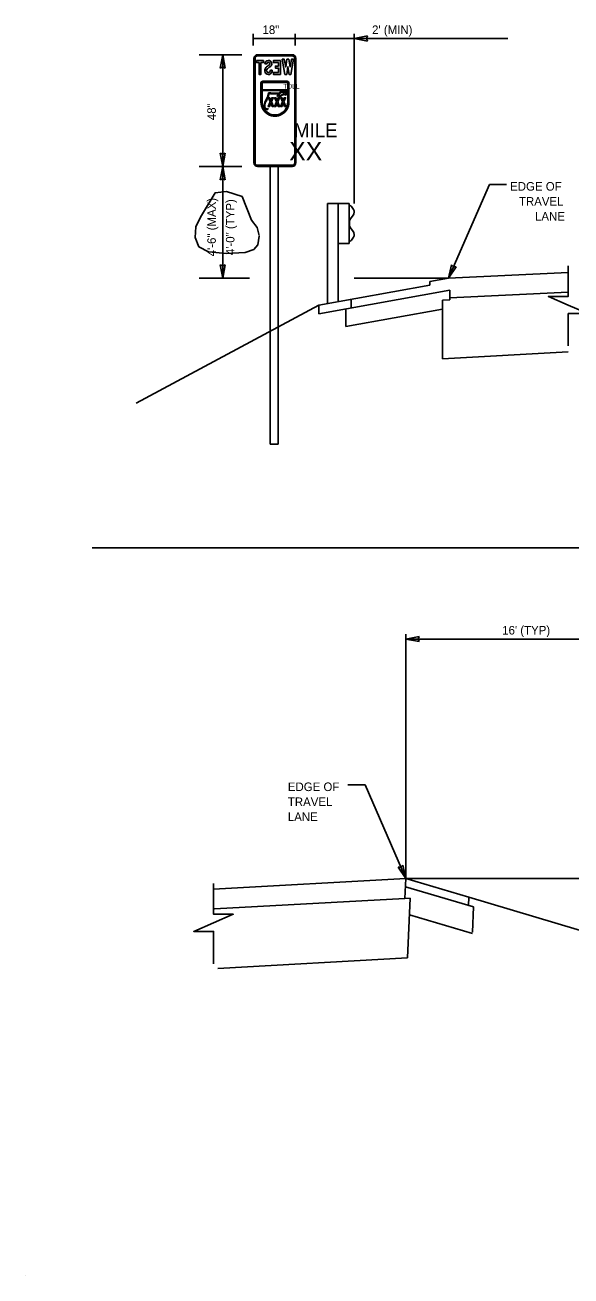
# Model space of a CAD drawing. Extents: x 56768 to 57406, y 11696 to 12105.
# Drawn here: x 56767.9 to 56946.4, y 11696.3 to 12105.2 of the extents above; entities that cross this region are included whole.
import ezdxf

# ---------------------------------------------------------------- set-up
doc = ezdxf.new("R2010")
doc.units = 0
for name, color, linetype in [('1', 7, 'Continuous'), ('52', 7, 'Continuous'), ('62', 7, 'Continuous'), ('AdhocPoint_dp', 7, 'Continuous'), ('Default', 7, 'Continuous'), ('DimLines_dp', 7, 'Continuous'), ('SheetBorder_dp', 7, 'Continuous'), ('SignPanel', 7, 'Continuous'), ('XSGrdLine_ex', 7, 'Continuous')]:
    doc.layers.add(name, color=color, linetype=linetype)

msp = doc.modelspace()

# ---------------------------------------------------------------- linework, layer by layer
at = {"layer": '1'}
for p, q in [((56848.03, 12005.09), (56848.03, 12058.97)), ((56850.69, 12006.52), (56850.69, 12058.97)), ((56848.03, 11968.2), (56848.03, 12005.09)), ((56850.69, 11968.2), (56850.69, 12006.52)), ((56850.69, 11968.2), (56848.03, 11968.2))]:
    msp.add_line(p, q, dxfattribs=at)
at = {"layer": '52'}
for p, q in [((56824.81, 12022.47), (56841.31, 12022.47)), ((56875.53, 12022.47), (56906.41, 12022.47)), ((56970.53, 11826.22), (56892.41, 11826.22))]:
    msp.add_line(p, q, dxfattribs=at)
at = {"layer": '62'}
msp.add_lwpolyline([(56844.47, 12036.41), (56843.77, 12039.01), (56841.97, 12041.42), (56838.86, 12049.17), (56833.76, 12050.77), (56830.06, 12050.27), (56825.26, 12042.42), (56823.76, 12039.21), (56823.56, 12035.71), (56824.76, 12032.7), (56827.86, 12031), (56833.76, 12030.5), (56839.86, 12030.8), (56842.67, 12031.8), (56844.07, 12033.31), (56844.47, 12036.21)], dxfattribs=at)
at = {"layer": 'AdhocPoint_dp'}
msp.add_line((56767.89, 11696.32), (56767.89, 11696.32), dxfattribs=at)
at = {"layer": 'Default'}
for points in [[(56945.5, 12000.28), (56945.5, 12010.84), (56951.96, 12010.84), (56945.5, 12013.65), (56939.04, 12016.47), (56945.5, 12016.47), (56945.5, 12026.47)], [(56829.53, 11798.37), (56829.53, 11808.93), (56823.07, 11808.93), (56829.53, 11811.74), (56835.99, 11814.56), (56829.53, 11814.56), (56829.53, 11824.56)]]:
    msp.add_lwpolyline(points, dxfattribs=at)
at = {"layer": 'DimLines_dp'}
for p, q in [((56842.51, 12098.47), (56842.51, 12102.3)), ((56856.2, 12098.47), (56856.2, 12102.3)), ((56875.53, 12046.89), (56875.53, 12102.3)), ((56856.2, 12100.75), (56842.51, 12100.75)), ((56856.2, 12100.75), (56925.74, 12100.75)), ((56875.53, 12100.75), (56879.88, 12101.59)), ((56879.88, 12099.94), (56875.53, 12100.75)), ((56879.88, 12101.59), (56879.55, 12100.75)), ((56879.55, 12100.75), (56879.88, 12099.94)), ((56824.81, 12095.47), (56838.74, 12095.47)), ((56831.74, 12091.12), (56832.55, 12095.47)), ((56832.55, 12095.47), (56832.55, 12058.97)), ((56832.55, 12095.47), (56833.39, 12091.12)), ((56832.55, 12091.45), (56831.74, 12091.12)), ((56833.39, 12091.12), (56832.55, 12091.45)), ((56832.55, 12058.97), (56831.71, 12063.32)), ((56831.71, 12063.32), (56832.55, 12062.99)), ((56832.55, 12058.97), (56831.71, 12063.32)), ((56831.71, 12063.32), (56832.55, 12062.99)), ((56832.55, 12062.99), (56833.36, 12063.32)), ((56833.36, 12063.32), (56832.55, 12058.97)), ((56832.55, 12062.99), (56833.36, 12063.32)), ((56833.36, 12063.32), (56832.55, 12058.97)), ((56824.81, 12058.97), (56838.74, 12058.97)), ((56831.74, 12054.62), (56832.55, 12058.97)), ((56832.55, 12058.97), (56832.55, 12022.47)), ((56832.55, 12058.97), (56833.39, 12054.62)), ((56832.55, 12054.95), (56831.74, 12054.62)), ((56833.39, 12054.62), (56832.55, 12054.95)), ((56919.73, 12053.08), (56906.41, 12022.46)), ((56925.38, 12053.08), (56919.73, 12053.08)), ((56832.55, 12022.47), (56831.71, 12026.82)), ((56831.71, 12026.82), (56832.55, 12026.49)), ((56832.55, 12026.49), (56833.36, 12026.82)), ((56833.36, 12026.82), (56832.55, 12022.47)), ((56906.41, 12022.46), (56907.37, 12026.79)), ((56908.89, 12026.13), (56906.41, 12022.46)), ((56907.37, 12026.79), (56908.01, 12026.15)), ((56908.01, 12026.15), (56908.89, 12026.13)), ((56892.41, 11826.22), (56892.41, 11906.05)), ((56896.76, 11905.31), (56892.41, 11904.5)), ((56892.41, 11904.5), (56896.76, 11903.66)), ((56973.53, 11904.5), (56892.41, 11904.5)), ((56896.43, 11904.5), (56896.76, 11905.31)), ((56896.76, 11903.66), (56896.43, 11904.5)), ((56873.44, 11856.84), (56879.09, 11856.84)), ((56879.09, 11856.84), (56892.41, 11826.22)), ((56890.8, 11829.91), (56889.93, 11829.89)), ((56889.93, 11829.89), (56892.41, 11826.22)), ((56891.44, 11830.55), (56890.8, 11829.91)), ((56892.41, 11826.22), (56891.44, 11830.55))]:
    msp.add_line(p, q, dxfattribs=at)
at = {"layer": 'SheetBorder_dp'}
msp.add_line((57405.89, 11934.25), (56789.89, 11934.25), dxfattribs=at)
at = {"layer": 'SignPanel'}
for p, q in [((56846.91, 12092.46), (56846.3, 12092.46)), ((56846.91, 12092.46), (56846.3, 12092.46)), ((56846.91, 12092.46), (56846.3, 12092.46)), ((56848.11, 12090.45), (56848.73, 12090.45)), ((56848.11, 12090.45), (56848.73, 12090.45)), ((56848.11, 12090.45), (56848.73, 12090.45)), ((56845.04, 12079.95), (56845.04, 12086.23)), ((56845.24, 12079.95), (56845.24, 12086.23)), ((56845.43, 12083.95), (56845.43, 12086.23)), ((56853.6, 12086.8), (56845.61, 12086.8)), ((56853.6, 12086.61), (56845.61, 12086.61)), ((56853.6, 12086.42), (56845.61, 12086.42)), ((56853.79, 12083.95), (56853.79, 12086.23)), ((56853.98, 12079.95), (56853.98, 12086.23)), ((56854.17, 12079.95), (56854.17, 12086.23)), ((56853.79, 12083.95), (56845.43, 12083.95)), ((56845.43, 12079.95), (56845.43, 12083.76)), ((56853.79, 12083.76), (56845.43, 12083.76)), ((56847.49, 12083.02), (56847.16, 12081.58)), ((56847.38, 12081.5), (56847.68, 12082.79)), ((56848.23, 12083.02), (56847.49, 12083.02)), ((56847.68, 12082.79), (56848.11, 12082.79)), ((56848.11, 12082.79), (56848.21, 12082.63)), ((56848.21, 12082.63), (56851.22, 12082.63)), ((56848.33, 12082.86), (56848.23, 12083.02)), ((56851.06, 12082.86), (56848.33, 12082.86)), ((56850.77, 12082.34), (56850.27, 12082)), ((56850.27, 12082), (56850.4, 12081.81)), ((56850.4, 12081.81), (56850.77, 12082.07)), ((56851.38, 12081.98), (56850.77, 12082.34)), ((56850.77, 12082.07), (56851.41, 12081.7)), ((56851.19, 12083.21), (56851.06, 12082.86)), ((56853.57, 12083.39), (56851.19, 12083.21)), ((56851.22, 12082.63), (56851.36, 12082.99)), ((56851.36, 12082.99), (56853.3, 12083.14)), ((56851.83, 12082.4), (56851.38, 12081.98)), ((56851.41, 12081.7), (56851.95, 12082.19)), ((56852.75, 12082.7), (56851.83, 12082.4)), ((56851.95, 12082.19), (56852.7, 12082.44)), ((56852.32, 12083.05), (56852.32, 12083.05)), ((56852.7, 12082.44), (56852.95, 12082.24)), ((56853.02, 12082.48), (56852.75, 12082.7)), ((56852.95, 12082.24), (56853.41, 12082.3)), ((56853.2, 12082.51), (56853.02, 12082.48)), ((56853.3, 12083.14), (56853.2, 12082.51)), ((56853.41, 12082.3), (56853.57, 12083.39)), ((56853.79, 12079.95), (56853.79, 12083.76)), ((56846.3, 12080), (56846.05, 12079.08)), ((56846.05, 12079.08), (56846.05, 12078.21)), ((56846.05, 12078.21), (56846.8, 12077.6)), ((56846.28, 12079.05), (56846.51, 12079.91)), ((56846.28, 12078.32), (56846.28, 12079.05)), ((56846.9, 12077.81), (56846.28, 12078.32)), ((56846.71, 12080.67), (56846.3, 12080)), ((56846.51, 12079.91), (56846.94, 12080.61)), ((56847.16, 12081.58), (56846.71, 12080.86)), ((56846.71, 12080.86), (56846.71, 12080.67)), ((56846.8, 12077.6), (56847.16, 12077.51)), ((56847.11, 12077.76), (56846.9, 12077.81)), ((56846.94, 12080.79), (56847.38, 12081.5)), ((56846.94, 12080.61), (56846.94, 12080.79)), ((56847.25, 12077.86), (56847.11, 12077.76)), ((56847.16, 12077.51), (56847.38, 12077.67)), ((56847.38, 12077.67), (56847.25, 12077.86))]:
    msp.add_line(p, q, dxfattribs=at)
for points in [[(56842.76, 12094.33), (56842.76, 12060.11)], [(56843.14, 12094.33), (56843.14, 12060.11)], [(56855.31, 12095.47), (56843.9, 12095.47)], [(56855.31, 12095.09), (56843.9, 12095.09)], [(56856.07, 12060.11), (56856.07, 12094.33)], [(56856.45, 12060.11), (56856.45, 12094.33)], [(56843.9, 12059.35), (56855.31, 12059.35)], [(56843.9, 12058.97), (56855.31, 12058.97)]]:
    msp.add_lwpolyline(points, dxfattribs=at)
for points in [[(56854.54, 12091.43), (56854.14, 12093.99), (56853.53, 12093.99), (56853.13, 12091.43), (56852.68, 12093.99), (56851.98, 12093.99), (56852.86, 12089.04), (56853.45, 12089.04), (56853.84, 12091.52), (56854.23, 12089.04), (56854.81, 12089.04), (56855.69, 12093.99), (56855, 12093.99)], [(56854.54, 12091.43), (56854.14, 12093.99), (56853.53, 12093.99), (56853.13, 12091.43), (56852.68, 12093.99), (56851.98, 12093.99), (56852.86, 12089.04), (56853.45, 12089.04), (56853.84, 12091.52), (56854.23, 12089.04), (56854.81, 12089.04), (56855.69, 12093.99), (56855, 12093.99)], [(56854.54, 12091.43), (56854.14, 12093.99), (56853.53, 12093.99), (56853.13, 12091.43), (56852.68, 12093.99), (56851.98, 12093.99), (56852.86, 12089.04), (56853.45, 12089.04), (56853.84, 12091.52), (56854.23, 12089.04), (56854.81, 12089.04), (56855.69, 12093.99), (56855, 12093.99)], [(56845.05, 12092.91), (56845.87, 12092.91), (56845.87, 12093.54), (56843.61, 12093.54), (56843.61, 12092.91), (56844.43, 12092.91), (56844.43, 12089.04), (56845.05, 12089.04)], [(56845.05, 12092.91), (56845.87, 12092.91), (56845.87, 12093.54), (56843.61, 12093.54), (56843.61, 12092.91), (56844.43, 12092.91), (56844.43, 12089.04), (56845.05, 12089.04)], [(56845.05, 12092.91), (56845.87, 12092.91), (56845.87, 12093.54), (56843.61, 12093.54), (56843.61, 12092.91), (56844.43, 12092.91), (56844.43, 12089.04), (56845.05, 12089.04)], [(56850.76, 12089.67), (56850.76, 12091.11), (56849.79, 12091.11), (56849.79, 12091.74), (56850.76, 12091.74), (56850.76, 12092.91), (56849.12, 12092.91), (56849.12, 12093.54), (56851.38, 12093.54), (56851.38, 12089.04), (56849.12, 12089.04), (56849.12, 12089.67)], [(56850.76, 12089.67), (56850.76, 12091.11), (56849.79, 12091.11), (56849.79, 12091.74), (56850.76, 12091.74), (56850.76, 12092.91), (56849.12, 12092.91), (56849.12, 12093.54), (56851.38, 12093.54), (56851.38, 12089.04), (56849.12, 12089.04), (56849.12, 12089.67)], [(56850.76, 12089.67), (56850.76, 12091.11), (56849.79, 12091.11), (56849.79, 12091.74), (56850.76, 12091.74), (56850.76, 12092.91), (56849.12, 12092.91), (56849.12, 12093.54), (56851.38, 12093.54), (56851.38, 12089.04), (56849.12, 12089.04), (56849.12, 12089.67)], [(56848.69, 12078.53), (56848.28, 12079.51), (56847.87, 12078.53), (56847.44, 12078.53), (56848.06, 12080.02), (56847.49, 12081.39), (56847.92, 12081.39), (56848.28, 12080.53), (56848.64, 12081.39), (56849.06, 12081.39), (56848.49, 12080.02), (56849.11, 12078.53)], [(56850.7, 12078.53), (56850.29, 12079.51), (56849.88, 12078.53), (56849.46, 12078.53), (56850.08, 12080.02), (56849.51, 12081.39), (56849.93, 12081.39), (56850.29, 12080.53), (56850.65, 12081.39), (56851.08, 12081.39), (56850.51, 12080.02), (56851.13, 12078.53)], [(56852.72, 12078.53), (56852.31, 12079.51), (56851.9, 12078.53), (56851.47, 12078.53), (56852.1, 12080.02), (56851.52, 12081.39), (56851.95, 12081.39), (56852.31, 12080.53), (56852.67, 12081.39), (56853.09, 12081.39), (56852.52, 12080.02), (56853.14, 12078.53)]]:
    msp.add_lwpolyline(points, close=True, dxfattribs=at)
for centre, radius, start, end in [((56843.9, 12094.33), 1.14, 90, 180), ((56843.9, 12094.33), 0.76, 90, 180), ((56855.31, 12094.33), 1.14, 0, 90), ((56855.31, 12094.33), 0.76, 0, 90), ((56843.9, 12060.11), 1.14, 180, 270), ((56843.9, 12060.11), 0.76, 180, 270), ((56855.31, 12060.11), 1.14, 270, 0), ((56855.31, 12060.11), 0.76, 270, 0)]:
    msp.add_arc(centre, radius, start, end, dxfattribs=at)
for centre, major_axis, ratio, start_param, end_param in [((56847.64, 12090.27), (0, -1.4), 0.981197, 3.939023, 5.163791), ((56847.64, 12090.27), (0, -1.4), 0.981197, 3.939023, 5.163791), ((56847.64, 12090.27), (0, -1.4), 0.981197, 3.939023, 5.163791), ((56847.45, 12092.43), (0, -1.17), 0.981197, 1.634182, 4.688511), ((56847.45, 12092.43), (0, -1.17), 0.981197, 1.634182, 4.688511), ((56847.45, 12092.43), (0, -1.17), 0.981197, 1.634182, 4.688511), ((56849.76, 12088.29), (0, -4.32), 0.981197, 3.642536, 3.961892), ((56849.76, 12088.29), (0, -4.32), 0.981197, 3.642536, 3.961892), ((56849.76, 12088.29), (0, -4.32), 0.981197, 3.642536, 3.961892), ((56847.65, 12090.27), (0, -0.78), 0.981197, 3.79238, 5.170369), ((56847.65, 12090.27), (0, -0.78), 0.981197, 3.79238, 5.170369), ((56847.65, 12090.27), (0, -0.78), 0.981197, 3.79238, 5.170369), ((56847.45, 12092.42), (0, -0.55), 0.981197, 2.28404, 4.637874), ((56847.45, 12092.42), (0, -0.55), 0.981197, 2.28404, 4.637874), ((56847.45, 12092.42), (0, -0.55), 0.981197, 2.28404, 4.637874), ((56847.46, 12090.19), (0, -0.572), 0.981197, 5.194718, 7.162991), ((56847.46, 12090.19), (0, -0.572), 0.981197, 5.194718, 7.162991), ((56847.46, 12090.19), (0, -0.572), 0.981197, 5.194718, 7.162991), ((56850.3, 12087.61), (0, -4.56), 0.981197, 3.63779, 3.909641), ((56850.3, 12087.61), (0, -4.56), 0.981197, 3.63779, 3.909641), ((56850.3, 12087.61), (0, -4.56), 0.981197, 3.63779, 3.909641), ((56847.52, 12092.49), (0, -0.453), 0.981197, 0.484634, 2.267813), ((56847.52, 12092.49), (0, -0.453), 0.981197, 0.484634, 2.267813), ((56847.52, 12092.49), (0, -0.453), 0.981197, 0.484634, 2.267813), ((56847.23, 12090.41), (0, -0.897), 0.981197, 0.859453, 1.616836), ((56847.29, 12090.39), (0, -1.47), 0.981197, 0.439911, 1.615229), ((56847.23, 12090.41), (0, -0.897), 0.981197, 0.859453, 1.616836), ((56847.29, 12090.39), (0, -1.47), 0.981197, 0.439911, 1.615229), ((56847.23, 12090.41), (0, -0.897), 0.981197, 0.859453, 1.616836), ((56847.29, 12090.39), (0, -1.47), 0.981197, 0.439911, 1.615229), ((56847.56, 12092.47), (0, -1.05), 0.981197, 0.629826, 1.606762), ((56847.56, 12092.47), (0, -1.05), 0.981197, 0.629826, 1.606762), ((56847.56, 12092.47), (0, -1.05), 0.981197, 0.629826, 1.606762), ((56845.62, 12086.23), (0, 0.57), 0.9997, 0, 1.570796), ((56845.62, 12086.23), (0, 0.38), 0.9997, 0, 1.570796), ((56845.62, 12086.23), (0, 0.19), 0.9997, 0, 1.570796), ((56847.49, 12090.2), (0, -1.23), 0.981197, 5.173086, 6.638731), ((56847.49, 12090.2), (0, -1.23), 0.981197, 5.173086, 6.638731), ((56847.49, 12090.2), (0, -1.23), 0.981197, 5.173086, 6.638731), ((56853.6, 12086.23), (0, 0.57), 0.9997, 4.712389, 6.283185), ((56853.6, 12086.23), (0, 0.38), 0.9997, 4.712389, 6.283185), ((56853.6, 12086.23), (0, 0.19), 0.9997, 4.712389, 6.283185), ((56849.61, 12079.95), (0, 4.56), 0.9997, 1.570796, 4.712389), ((56849.61, 12079.95), (0, 4.37), 0.9997, 1.570796, 4.712389), ((56849.61, 12079.95), (0, 4.18), 0.9997, 1.570796, 4.712389)]:
    msp.add_ellipse(centre, major_axis=major_axis, ratio=ratio, start_param=start_param, end_param=end_param, dxfattribs=at)
at = {"layer": 'XSGrdLine_ex'}
for p, q in [((56866.81, 12014.16), (56866.81, 12046.89)), ((56866.81, 12046.89), (56873.91, 12046.89)), ((56870.3, 12014.79), (56870.3, 12046.89)), ((56873.91, 12033.81), (56873.91, 12046.89)), ((56873.92, 12046.32), (56874.39, 12046.1)), ((56874.62, 12045.89), (56875.31, 12044.85)), ((56873.99, 12040.92), (56873.99, 12039.81)), ((56874.21, 12041.73), (56875.28, 12043.14)), ((56874.21, 12039.02), (56875.28, 12037.61)), ((56870.3, 12033.81), (56873.91, 12033.81)), ((56873.92, 12034.41), (56874.39, 12034.62)), ((56874.62, 12034.86), (56875.31, 12035.88)), ((56906.41, 12022.46), (56900.25, 12021.36)), ((56900.25, 12021.36), (56900.25, 12020.18)), ((56900.25, 12020.18), (56863.97, 12013.65)), ((56863.97, 12010.81), (56906.82, 12018.53)), ((56906.82, 12018.53), (56906.82, 12015.37)), ((56863.97, 12013.65), (56804.25, 11981.59)), ((56863.97, 12013.65), (56863.97, 12010.81)), ((56872.83, 12012.41), (56872.83, 12006.59)), ((56904.35, 12012.26), (56872.83, 12006.59)), ((56874.53, 12015.55), (56874.53, 12012.71)), ((56906.82, 12015.37), (56904.35, 12015.22)), ((56904.35, 12015.22), (56904.35, 11996.05)), ((56945.5, 11998.32), (56904.35, 11996.05)), ((56892.41, 11826.22), (56829.53, 11822.74)), ((56892.12, 11819.71), (56892.41, 11826.22)), ((56892.41, 11826.22), (56913.04, 11820.09)), ((56892.29, 11823.55), (56914.58, 11816.92)), ((56913.04, 11820.09), (56912.93, 11817.42)), ((56978.01, 11800.77), (56913.04, 11820.09)), ((56829.88, 11816.26), (56892.12, 11819.71)), ((56893.87, 11819.8), (56892.12, 11819.71)), ((56893, 11800.26), (56893.87, 11819.8)), ((56914.58, 11816.92), (56914.21, 11808.7)), ((56893.63, 11814.4), (56914.19, 11808.28)), ((56893, 11800.26), (56830.96, 11796.82))]:
    msp.add_line(p, q, dxfattribs=at)
for points in [[(56945.5, 12024.32), (56906.41, 12022.46)], [(56945.5, 12017.82), (56906.82, 12015.99)]]:
    msp.add_lwpolyline(points, dxfattribs=at)
for centre, major_axis, start_param, end_param in [((56874.24, 12044.85), (0, 1.28), 5.646537, 6.041895), ((56875, 12044.01), (0, -1.05), 0.577206, 2.505315), ((56874.48, 12040.9), (0, -0.976), 3.718758, 4.701029), ((56874.48, 12039.82), (0, -0.976), 4.723749, 5.70602), ((56875, 12036.72), (0, 1.05), 3.777871, 5.70598), ((56874.24, 12035.88), (0, -1.28), 0.24129, 0.636649)]:
    msp.add_ellipse(centre, major_axis=major_axis, ratio=0.5, start_param=start_param, end_param=end_param, dxfattribs=at)

# ---------------------------------------------------------------- texts
at = {"layer": 'DimLines_dp'}
for s, p in [('18"', (56845.55, 12102.22)), ("2' (MIN)", (56881.38, 12102.22)), ('EDGE OF ', (56926.52, 12051.04)), ('TRAVEL ', (56929.39, 12046.14)), ('LANE', (56934.65, 12041.24)), ("16' (TYP)", (56923.92, 11905.97)), ('EDGE OF ', (56853.83, 11854.8)), ('TRAVEL ', (56853.83, 11849.9)), ('LANE', (56853.83, 11845))]:
    msp.add_text(s, height=2.8, dxfattribs=at).set_placement(p)
for s, p in [('48"', (56830.29, 12074.08)), ('4\'-6" (MAX)', (56830.29, 12029.57)), ('4\'-0" (TYP)', (56836.38, 12029.97))]:
    msp.add_text(s, height=2.8, rotation=90, dxfattribs=at).set_placement(p)
at = {"layer": 'SignPanel'}
for s, height, p in [('TOLL', 1.519, (56852.36, 12084.42)), ('MILE', 4.562, (56855.86, 12068.47)), ('XX', 6.083, (56854.25, 12060.9))]:
    msp.add_text(s, height=height, dxfattribs=at).set_placement(p)

doc.saveas('drawing.dxf')
